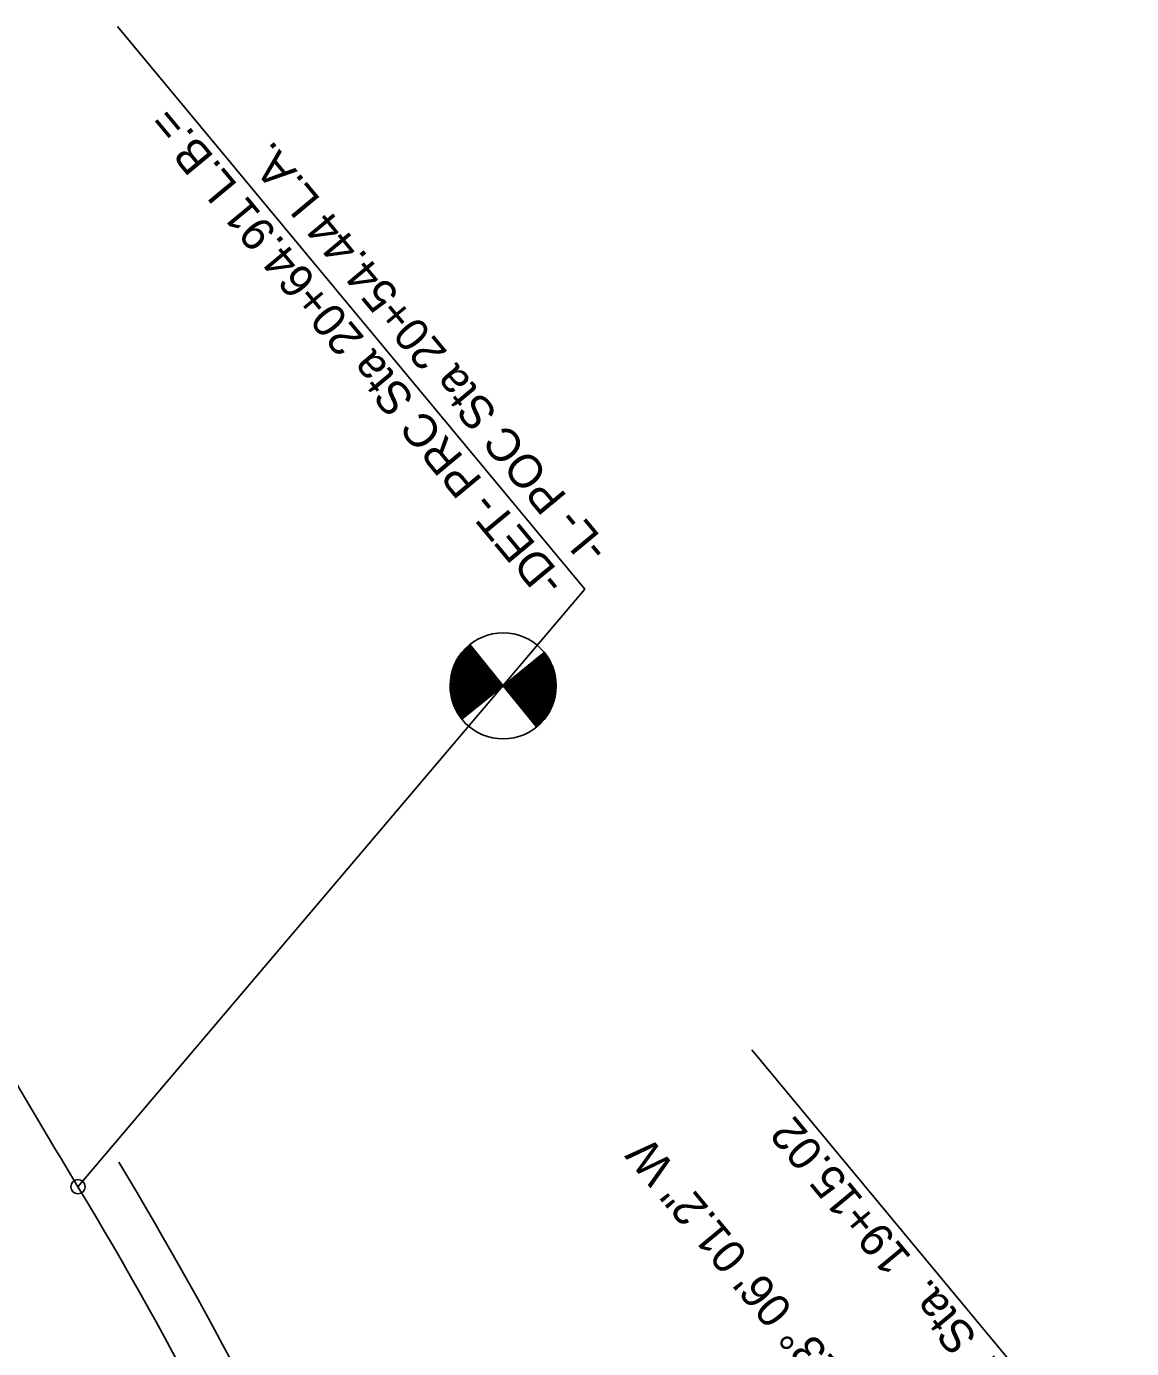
# Model space of a CAD drawing. Extents: x 2597390 to 2598563, y 852595 to 853909.
# Drawn here: x 2597727.6 to 2597960.9, y 853629.4 to 853908.5 of the extents above; entities that cross this region are included whole.
import ezdxf

# ---------------------------------------------------------------- set-up
doc = ezdxf.new("R2010")
doc.units = 0
for name, color, linetype in [('Prop Horizontal Alignment', 7, 'Continuous'), ('Prop Horizontal Alignment Direction Label', 7, 'Continuous'), ('Prop Horizontal Alignment Station Label', 7, 'Continuous'), ('Prop Lane Lines', 7, 'Continuous'), ('Typical Grade Point Symbol CELL', 7, 'Continuous')]:
    doc.layers.add(name, color=color, linetype=linetype)

msp = doc.modelspace()

# ---------------------------------------------------------------- linework, layer by layer
at = {"layer": 'Prop Horizontal Alignment'}
for centre, radius, start, end in [((2599247.12, 854575.63), 1762.95, 209.28143, 211.1561), ((2597025.61, 853232.56), 833, 23.10033, 31.1561)]:
    msp.add_arc(centre, radius, start, end, dxfattribs=at)
at = {"layer": 'Prop Horizontal Alignment Station Label'}
for p, q in [((2597845.5, 853789.67), (2597746.81, 853908.51)), ((2597738.46, 853663.53), (2597845.5, 853789.67)), ((2597960.9, 853595.87), (2597880.7, 853692.45))]:
    msp.add_line(p, q, dxfattribs=at)
msp.add_circle((2597738.46, 853663.53), 1.5, dxfattribs=at)
at = {"layer": 'Prop Lane Lines'}
msp.add_arc((2597025.61, 853232.56), 843.05, 23.10033, 31.1561, dxfattribs=at)
at = {"layer": 'Typical Grade Point Symbol CELL'}
for p, q in [((2597821.16, 853777.98), (2597828.21, 853769.3)), ((2597836.91, 853776.33), (2597828.21, 853769.3)), ((2597828.21, 853769.3), (2597836.91, 853776.33)), ((2597828.21, 853769.3), (2597819.53, 853762.24)), ((2597835.27, 853760.61), (2597828.21, 853769.3))]:
    msp.add_line(p, q, dxfattribs=at)
for points in [[(2597818.19, 853774.25), (2597821.8, 853777.19)], [(2597818.45, 853774.76), (2597821.66, 853777.36)], [(2597818.8, 853775.32), (2597821.52, 853777.54)], [(2597819.25, 853775.98), (2597821.38, 853777.71)], [(2597820, 853776.88), (2597821.23, 853777.88)], [(2597817.02, 853769.27), (2597823.77, 853774.76)], [(2597817.03, 853769.57), (2597823.63, 853774.93)], [(2597817.03, 853768.98), (2597823.92, 853774.58)], [(2597817.05, 853769.86), (2597823.49, 853775.1)], [(2597817.05, 853768.72), (2597824.06, 853774.41)], [(2597817.06, 853770.16), (2597823.35, 853775.28)], [(2597817.09, 853770.48), (2597823.21, 853775.45)], [(2597817.13, 853770.79), (2597823.07, 853775.62)], [(2597817.18, 853771.12), (2597822.93, 853775.8)], [(2597817.25, 853771.47), (2597822.79, 853775.97)], [(2597817.32, 853771.82), (2597822.65, 853776.15)], [(2597817.41, 853772.18), (2597822.5, 853776.32)], [(2597817.52, 853772.56), (2597822.36, 853776.49)], [(2597817.65, 853772.95), (2597822.22, 853776.67)], [(2597817.8, 853773.36), (2597822.08, 853776.84)], [(2597817.97, 853773.78), (2597821.94, 853777.01)], [(2597828.32, 853769.16), (2597837.01, 853776.22), (2597837.01, 853776.22)], [(2597828.46, 853768.99), (2597837.15, 853776.04)], [(2597828.61, 853768.81), (2597837.27, 853775.86)], [(2597828.75, 853768.64), (2597837.41, 853775.68)], [(2597828.89, 853768.47), (2597837.53, 853775.49)], [(2597829.03, 853768.29), (2597837.65, 853775.3)], [(2597829.17, 853768.12), (2597837.78, 853775.11)], [(2597829.31, 853767.94), (2597837.88, 853774.91)], [(2597829.45, 853767.77), (2597838, 853774.72)], [(2597829.59, 853767.6), (2597838.1, 853774.51)], [(2597817.06, 853768.43), (2597824.2, 853774.24)], [(2597817.08, 853768.16), (2597824.34, 853774.06)], [(2597817.11, 853767.9), (2597824.48, 853773.89)], [(2597817.15, 853767.64), (2597824.62, 853773.71)], [(2597817.2, 853767.39), (2597824.76, 853773.54)], [(2597817.24, 853767.14), (2597824.9, 853773.37)], [(2597817.29, 853766.89), (2597825.05, 853773.19)], [(2597817.35, 853766.65), (2597825.19, 853773.02)], [(2597817.42, 853766.42), (2597825.33, 853772.85)], [(2597817.48, 853766.18), (2597825.47, 853772.67)], [(2597817.54, 853765.94), (2597825.61, 853772.5)], [(2597817.61, 853765.71), (2597825.75, 853772.33)], [(2597817.69, 853765.49), (2597825.89, 853772.15)], [(2597817.77, 853765.27), (2597826.03, 853771.98)], [(2597817.86, 853765.04), (2597826.18, 853771.8)], [(2597817.96, 853764.84), (2597826.32, 853771.63)], [(2597829.73, 853767.42), (2597838.21, 853774.31)], [(2597829.88, 853767.25), (2597838.31, 853774.1)], [(2597830.02, 853767.08), (2597838.41, 853773.9)], [(2597830.16, 853766.9), (2597838.49, 853773.68)], [(2597830.3, 853766.73), (2597838.6, 853773.47)], [(2597830.44, 853766.56), (2597838.68, 853773.25)], [(2597830.58, 853766.38), (2597838.76, 853773.03)], [(2597830.72, 853766.21), (2597838.85, 853772.81)], [(2597830.86, 853766.03), (2597838.91, 853772.57)], [(2597831, 853765.86), (2597838.97, 853772.34)], [(2597831.15, 853765.69), (2597839.04, 853772.1)], [(2597831.29, 853765.51), (2597839.1, 853771.87)], [(2597831.43, 853765.34), (2597839.17, 853771.63)], [(2597818.04, 853764.62), (2597826.46, 853771.46)], [(2597818.15, 853764.41), (2597826.6, 853771.28)], [(2597818.25, 853764.21), (2597826.74, 853771.11)], [(2597818.35, 853764), (2597826.88, 853770.94)], [(2597818.45, 853763.8), (2597827.02, 853770.76)], [(2597818.58, 853763.61), (2597827.16, 853770.59)], [(2597818.7, 853763.42), (2597827.3, 853770.41)], [(2597818.82, 853763.23), (2597827.45, 853770.24)], [(2597818.94, 853763.04), (2597827.59, 853770.07)], [(2597819.06, 853762.85), (2597827.73, 853769.89)], [(2597819.2, 853762.68), (2597827.87, 853769.72)], [(2597819.33, 853762.49), (2597828.01, 853769.55)], [(2597819.47, 853762.32), (2597819.47, 853762.32), (2597828.15, 853769.37)], [(2597831.57, 853765.17), (2597839.21, 853771.38)], [(2597831.71, 853764.99), (2597839.26, 853771.12)], [(2597831.85, 853764.82), (2597839.3, 853770.87)], [(2597831.99, 853764.65), (2597839.33, 853770.6)], [(2597832.13, 853764.47), (2597839.35, 853770.34)], [(2597832.28, 853764.3), (2597839.38, 853770.07)], [(2597832.42, 853764.12), (2597839.4, 853769.8)], [(2597832.56, 853763.95), (2597839.41, 853769.52)], [(2597832.7, 853763.78), (2597839.41, 853769.23)], [(2597832.84, 853763.6), (2597839.4, 853768.94)], [(2597832.98, 853763.43), (2597839.39, 853768.64)], [(2597833.12, 853763.26), (2597839.37, 853768.34)], [(2597833.26, 853763.08), (2597839.34, 853768.02)], [(2597833.4, 853762.91), (2597839.29, 853767.69)], [(2597833.55, 853762.73), (2597839.24, 853767.36)], [(2597833.69, 853762.56), (2597839.17, 853767.01)], [(2597833.83, 853762.39), (2597839.1, 853766.67)], [(2597833.97, 853762.21), (2597839.01, 853766.31)], [(2597834.11, 853762.04), (2597838.89, 853765.93)], [(2597834.25, 853761.87), (2597838.77, 853765.54)], [(2597834.39, 853761.69), (2597838.6, 853765.11)], [(2597834.53, 853761.52), (2597838.41, 853764.67)], [(2597834.68, 853761.35), (2597838.19, 853764.2)], [(2597834.82, 853761.17), (2597837.92, 853763.7)], [(2597834.96, 853761), (2597837.54, 853763.1)], [(2597835.1, 853760.82), (2597837.07, 853762.42)], [(2597835.24, 853760.65), (2597836.18, 853761.42)]]:
    msp.add_lwpolyline(points, dxfattribs=at)
msp.add_circle((2597828.22, 853769.28), 11.19, dxfattribs=at)
for start, end in [(129.0933, 219.0933), (309.0933, 39.0933)]:
    msp.add_arc((2597828.22, 853769.28), 11.19, start, end, dxfattribs=at)

# ---------------------------------------------------------------- texts
at = {"layer": 'Prop Horizontal Alignment Direction Label'}
msp.add_text('N 23%%d 06\' 01.2" W', height=7, rotation=129.7067, dxfattribs=at).set_placement((2597906.32, 853617.57))
at = {"layer": 'Prop Horizontal Alignment Station Label'}
for s, p in [('-DET- PRC Sta 20+64.91 L.B.=', (2597841.67, 853791.51)), ('-L- POC Sta 20+54.44 L.A. ', (2597850.89, 853798.47)), ('-DET- PT Sta.  19+15.02', (2597955.53, 853599.39))]:
    msp.add_text(s, height=7, rotation=129.7067, dxfattribs=at).set_placement(p)

doc.saveas('drawing.dxf')
